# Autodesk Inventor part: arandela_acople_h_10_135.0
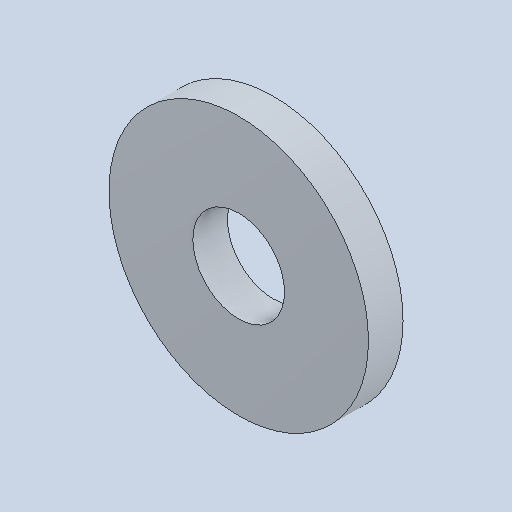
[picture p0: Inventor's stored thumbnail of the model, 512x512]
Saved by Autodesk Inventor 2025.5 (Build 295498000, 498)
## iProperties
Created: 2026-10
Part Number: arandela_acople_h_10_135.0
Material: Genérico
Document SubType Name: Modeling
Designer: Luis M
Density: 1 g/cm^3
Appearance: Valor por defecto
Author: Luis M
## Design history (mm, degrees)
feature "Base1"
node "Sólido1"
